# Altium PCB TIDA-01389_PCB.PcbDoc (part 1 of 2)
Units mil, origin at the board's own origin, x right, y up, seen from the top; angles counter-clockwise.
Board outline 3030.03 x 3369.98 mil, 2 copper layers (Top Layer, Bottom Layer), stack 62 mil thick; 50 components, 45 nets, 172 pads, 343 vias.
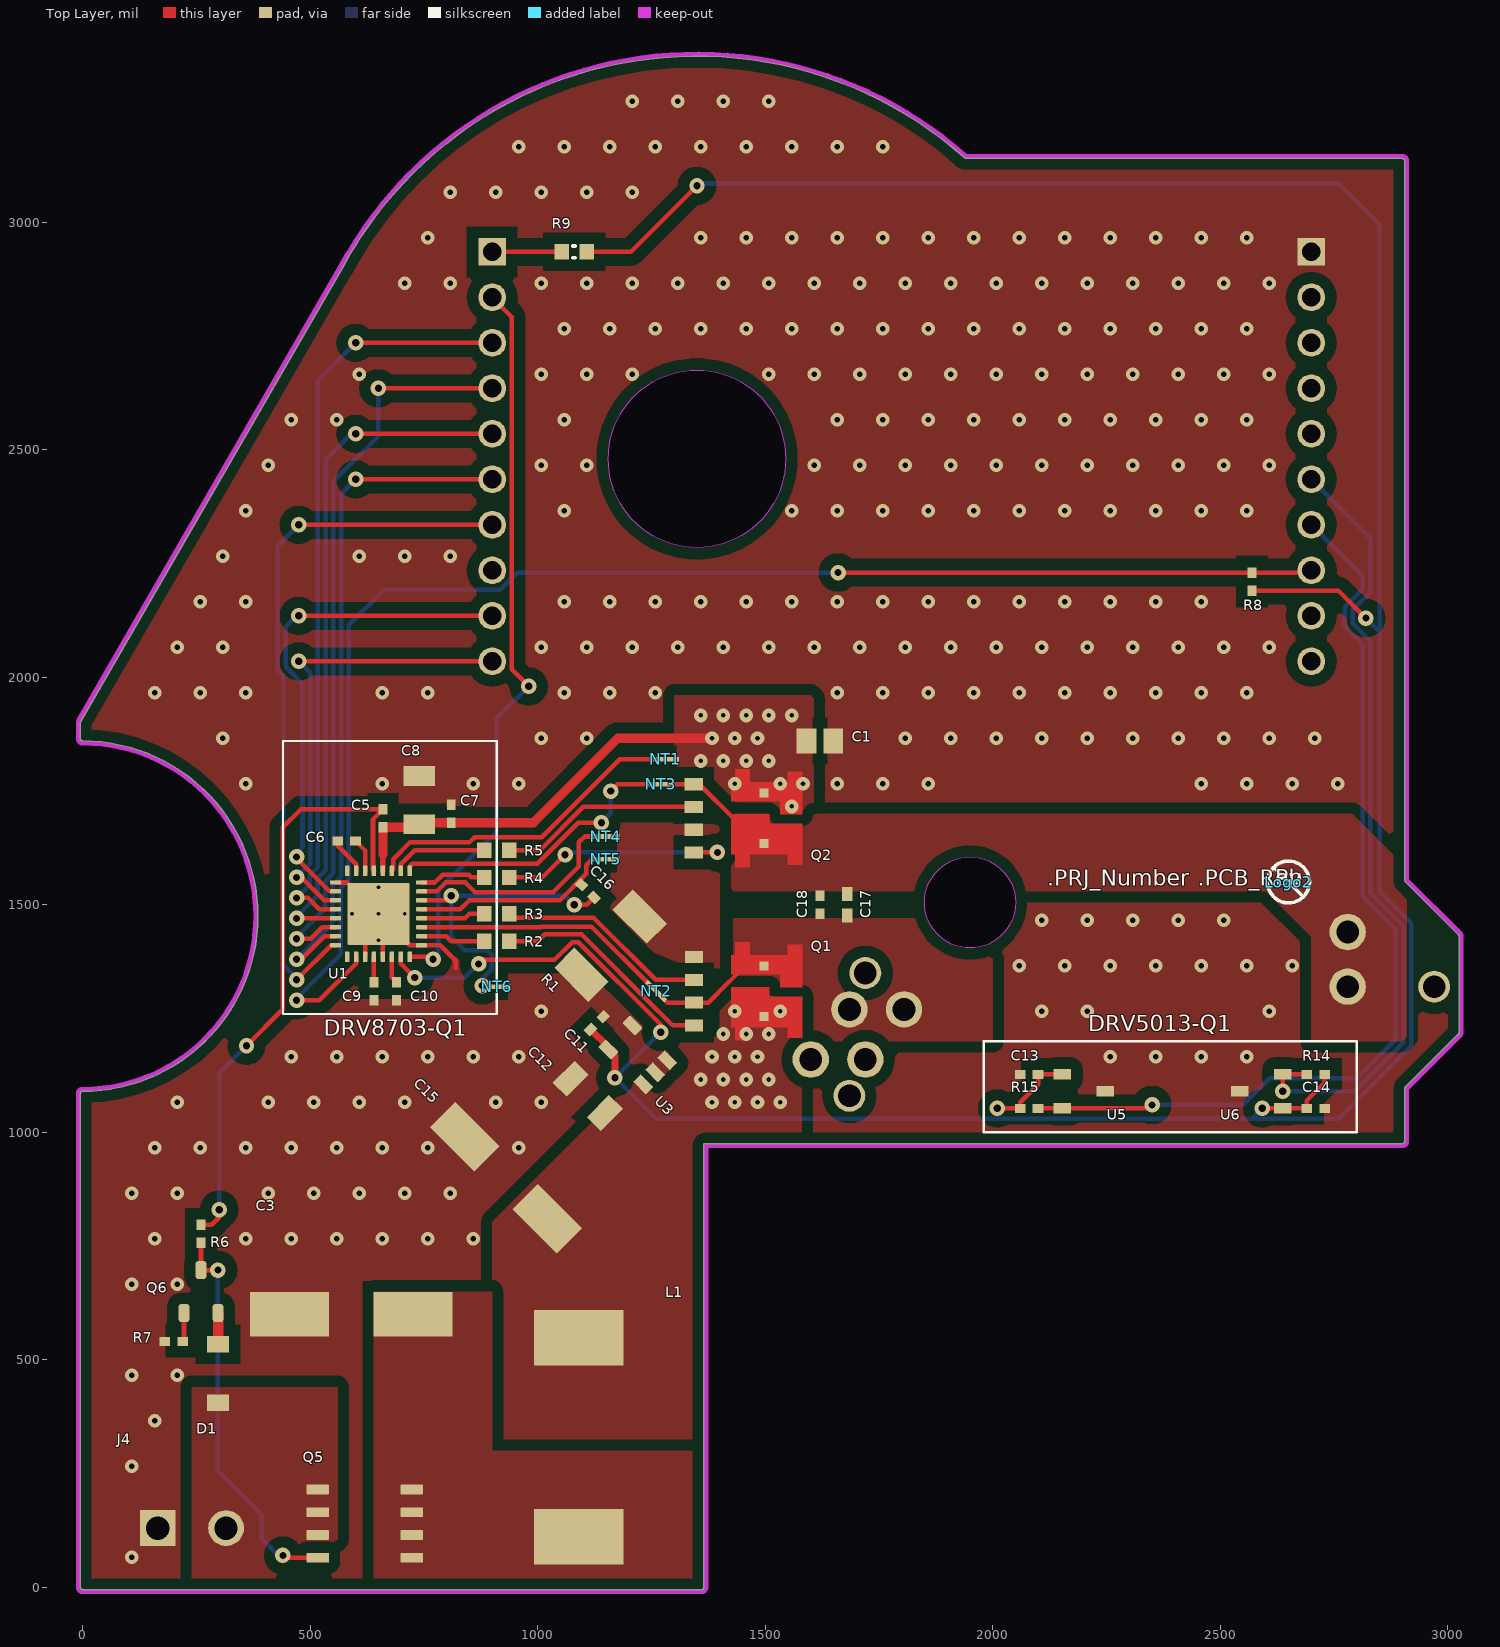
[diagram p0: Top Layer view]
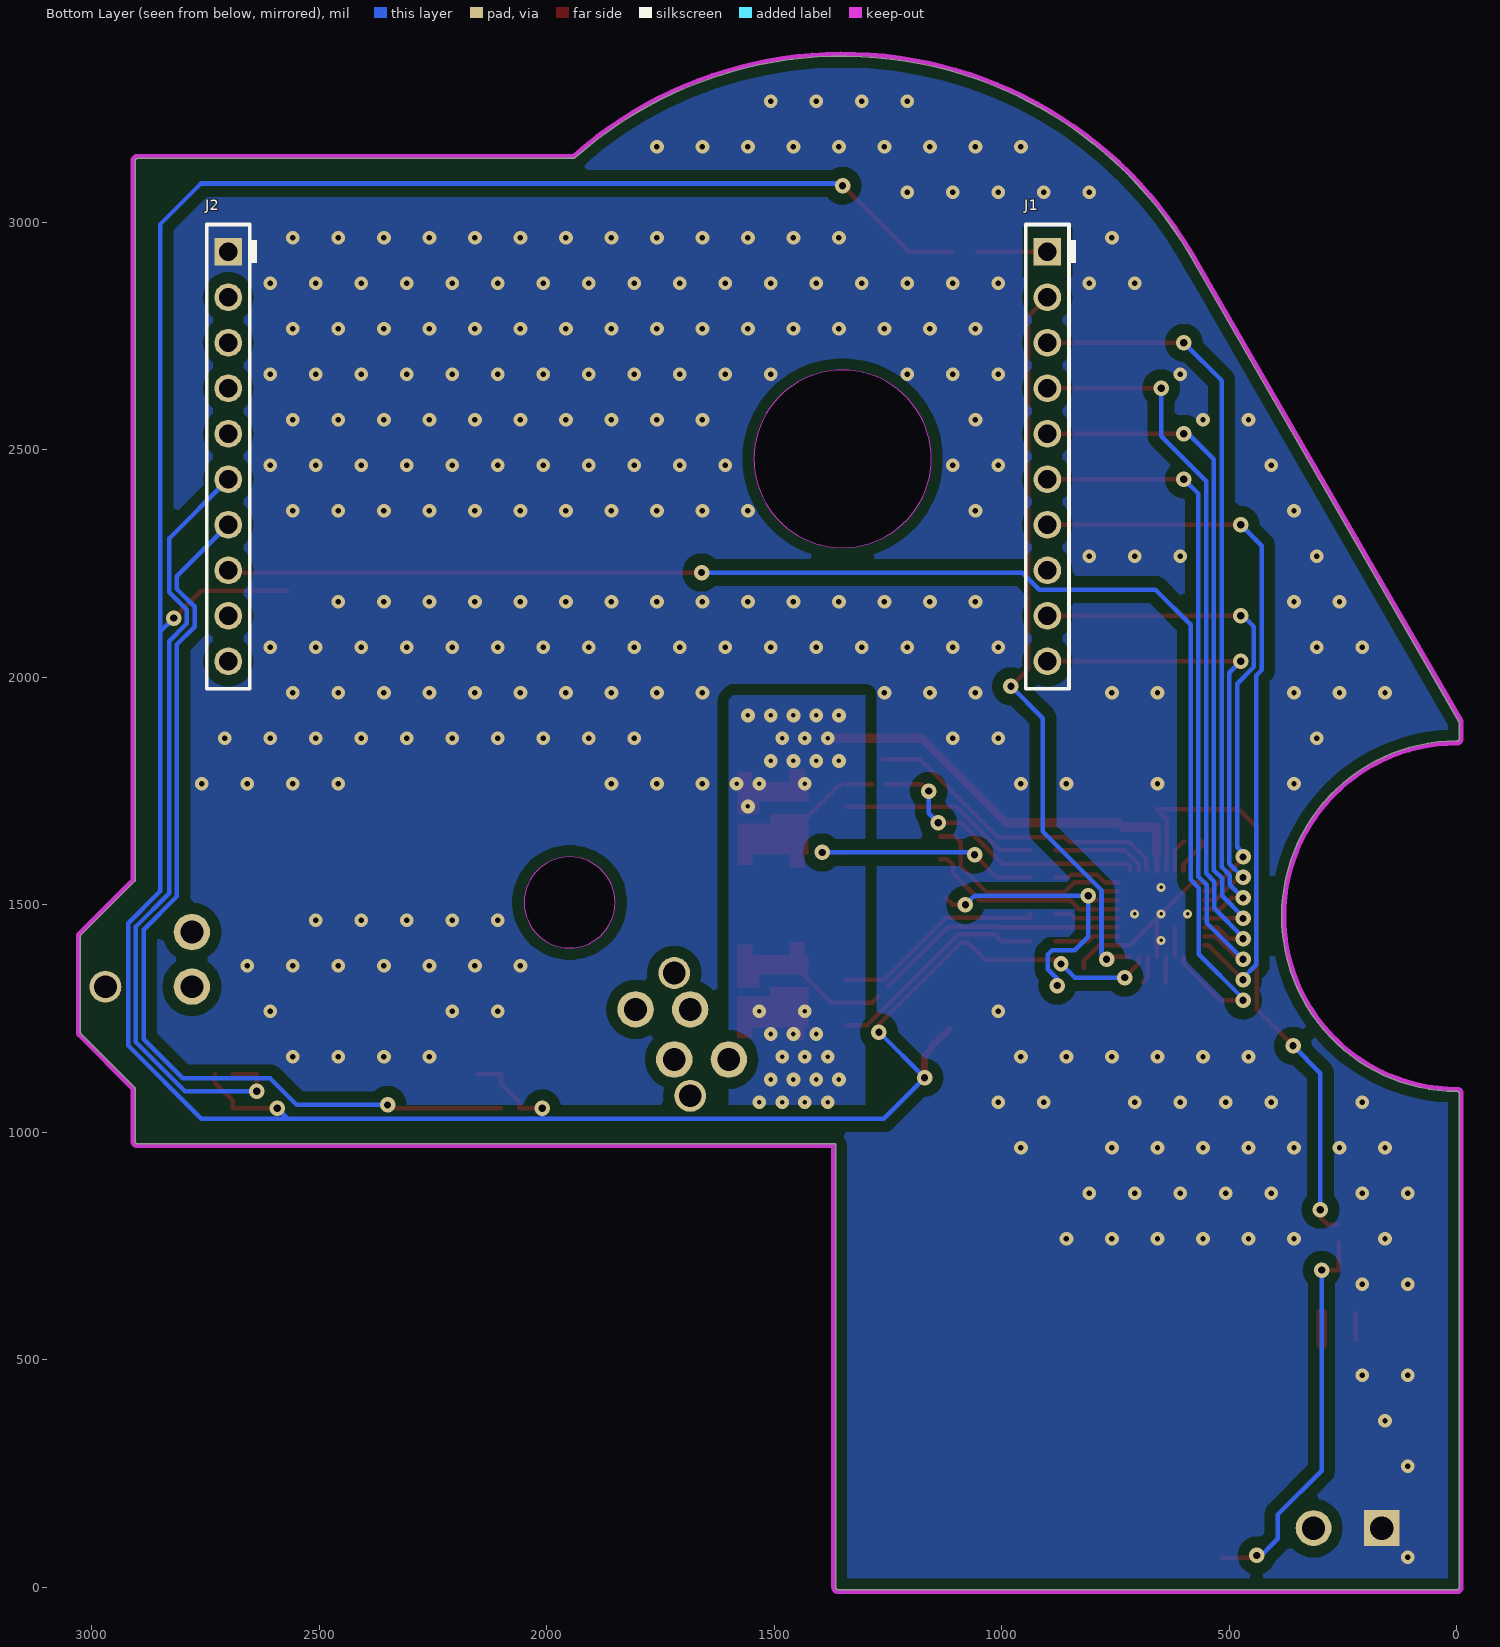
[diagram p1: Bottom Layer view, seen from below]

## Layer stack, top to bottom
Top Solder: solder mask 0.4, Solder Resist, Dk 3.5
Top Layer: signal copper 1.4
Dielectric1: core 59.2, FR-4, Dk 4.8
Bottom Layer: signal copper 1.4
Bottom Solder: solder mask 0.4, Solder Resist, Dk 3.5

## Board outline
0,-5.02 cw(c0,0) -5.02,0.13 -5.02,1085 cw(c0,1085) 0,1090.01 ccw(c0,1475) 384.98,1475 ccw(c0,1475) 0,1859.98 cw(c0,1865) -5.02,1865 -5.02,1900 cw(c0,1900) -4.34,1902.51 571.13,2900.26 cw(c1350,2480) 1936.71,3142.58 cw(c1933.39,3138.83) 1936.95,3142.36 1936.94,3142.37 1939.3,3140.01 2900,3140.01 cw(c2900,3135) 2905.01,3135 2905.01,1552.08 3023.55,1433.55 3023.53,1433.56 cw(c3020,1430) 3025.01,1430 3025.01,1220 cw(c3020,1220) 3023.53,1216.44 3023.55,1216.45 2905.01,1097.92 2905.01,980 cw(c2900,980) 2900,974.98 1365.01,974.98 1365.01,0 cw(c1360,0) 1360,-5.02
cut-out: 1350,2285 cw(c1350,2480) 1155,2480 cw(c1350,2480) 1350,2675 cw(c1350,2480) 1545,2480 cw(c1350,2480)
cut-out: 1950,1405 cw(c1950,1505) 1850,1505 cw(c1950,1505) 1950,1605 cw(c1950,1505) 2050,1505 cw(c1950,1505)

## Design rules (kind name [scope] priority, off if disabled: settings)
AcuteAngle [All] p1: minimum=4.50000000000000E+0001 checktracksonly=FALSE
AssemblyTestPointUsage [All] p1: valid=2
Clearance Clearance_Keepouts [((IsTrack Or IsArc) And Not InPoly) And IsFree and IsKeepOut vs ((IsTrack Or IsArc) And Not InPoly) And IsFree and IsKeepOut] p1: gap=0
Clearance Clearance_BoardEdge_MountingHoles [OnCopper and InComponentClass('Mounting Holes') vs IsKeepOut] p2: gap=40
Clearance Clearance_BoardEdge_Poly [OnCopper and InPoly vs IsKeepOut] p3: gap=25
Clearance Clearance_BoardEdge [OnCopper and Not InComponentClass('Logo') and not InComponentClass('FiducialMark') and not InRegion(1000,500,4000,800) and Not IsKeepout vs IsKeepOut] p4: gap=50
Clearance Clearance_Poly [InPolygon] p5: gap=25
Clearance [All] p6: gap=7
ComponentClearance ComponentClearance_MountingHoles_FiducialMarks [InComponentClass('Mounting Holes') vs InComponentClass('FiducialMark')] p1: gap=50 collisioncheckmode=3 verticalgap=10 showdistances=FALSE
ComponentClearance ComponentClearance_Shunt [InComponentClass('Header') vs InComponentClass('Shunt')] p2: gap=0 collisioncheckmode=3 verticalgap=0 showdistances=FALSE
ComponentClearance ComponentClearance_Logo [InComponentClass('Logo')] p3: gap=50 collisioncheckmode=3 verticalgap=10 showdistances=FALSE
ComponentClearance ComponentClearance_ScrewToNut [(HasFootprint('NY PMS 440 0025 PH')) vs (HasFootprint('Keystone_1902C'))] p4: gap=5 collisioncheckmode=3 verticalgap=10 showdistances=FALSE
ComponentClearance ComponentClearance_MountingHoles [InComponentClass('Mounting Holes')] p5: gap=250 collisioncheckmode=3 verticalgap=100000 showdistances=FALSE
ComponentClearance ComponentClearance_SmallPassives [HasFootprint('0201*') or HasFootprint('0402*') or HasFootprint('0508') or HasFootprint('0603*') or HasFootprint('0612') or HasFootprint('0805*') or HasFootprint('0815*') or HasFootprint('0830*') or HasFootprint('1206*') or HasFootprint('1210*') or HasFootprint('1808*') or HasFootprint('1812*') or HasFootprint('1825*') or HasFootprint('2010*') or HasFootprint('2220*') or HasFootprint('2225*') or HasFootprint('2512*') or HasFootprint('2728*') or HasFootprint('3518*') vs HasFootprint('0201*') or HasFootprint('0402*') or HasFootprint('0508') or HasFootprint('0603*') or HasFootprint('0612') or HasFootprint('0805*') or HasFootprint('0815*') or HasFootprint('0830*') or HasFootprint('1206*') or HasFootprint('1210*') or HasFootprint('1808*') or HasFootprint('1812*') or HasFootprint('1825*') or HasFootprint('2010*') or HasFootprint('2220*') or HasFootprint('2225*') or HasFootprint('2512*') or HasFootprint('2728*') or HasFootprint('3518*')] p6: gap=20 collisioncheckmode=3 verticalgap=10 showdistances=FALSE
ComponentClearance ComponentClearance_THtoSMT [IsThruComponent vs IsSMTComponent] p7: gap=100 collisioncheckmode=3 verticalgap=30 showdistances=FALSE
ComponentClearance ComponentClearance_THtoTH [IsThruComponent vs IsThruComponent] p8: gap=118.11 collisioncheckmode=3 verticalgap=30 showdistances=FALSE
ComponentClearance [All] p9: gap=40 collisioncheckmode=3 verticalgap=10 showdistances=FALSE
DiffPairsRouting [All] p1: maxlimit=100 minlimit=10 mostfreqgap=10 toplayer_minwidth=15 toplayer_maxwidth=15 toplayer_prefwidth=15 bottomlayer_minwidth=15 bottomlayer_maxwidth=15 bottomlayer_prefwidth=15 maxuncoupledlength=1000
FabricationTestPointUsage TestPointUsage [All] p1: valid=2 allowmultiple=FALSE
FabricationTestpoint Testpoint [All] p1: side=3 testpointundercomponent=TRUE minsize=40 maxsize=100 preferedsize=60 minholesize=0 maxholesize=40 preferedholesize=32 testpointgrid=1 allowsidetop=TRUE allowsidebottom=TRUE usegrid=TRUE gridtolerance=0.01
FanoutControl Fanout_LCC [IsLCC] p1: bgadir=Out bgaviamode=Centered fanoutstyle=Auto fanoutdirection=Alternating viagrid=1 // Fanout_LCC (Default Rule)
FanoutControl Fanout_BGA [IsBGA] p2: bgadir=Out bgaviamode=Centered fanoutstyle=Auto fanoutdirection=Alternating viagrid=1 // Fanout_BGA (Default Rule)
FanoutControl Fanout_Default [All] p4: bgadir=Out bgaviamode=Centered fanoutstyle=Auto fanoutdirection=Alternating viagrid=1 // Fanout_Default (Default Rule)
FanoutControl Fanout_Small [(CompPinCount < 5)] p5: bgadir=Out bgaviamode=Centered fanoutstyle=Auto fanoutdirection=OutThenIn viagrid=1 // Fanout_Small (Default Rule)
HoleSize [All] p1: absolutevalues=TRUE maxlimit=251 minlimit=7.5 maxpercent=80.000 minpercent=20.000
MinimumAnnularRing MinimumAnnularRing_ThermalPadVias [IsVia and InAnyComponent] p1: minimumring=5.91
MinimumAnnularRing [All] p2: minimumring=9
MinimumSolderMaskSliver MinimumSolderMaskSliver_Logo [InComponentClass('Logo') vs InComponentClass('Logo')] p1: minsoldermaskwidth=0.7
MinimumSolderMaskSliver [All] p2: minsoldermaskwidth=3.94
PlaneConnect [All] p1: planeconnectstyle=Direct reliefexpansion=10 reliefentries=4 reliefconductorwidth=10 reliefairgap=10
PolygonConnect [All] p1: connectstyle=Direct reliefconductorwidth=10 reliefentries=4 polygonreliefangle="90 Angle" airgapwidth=10
RoutingVias ThermalPadVias [IsVia and InAnyComponent] p1: holewidth=7.87 width=19.68 viastyle="Through Hole" minholewidth=7.87 minwidth=19.68 maxholewidth=12.99 maxwidth=23.62
RoutingVias [All] p2: holewidth=16 width=34 viastyle="Through Hole" minholewidth=7.87 minwidth=26 maxholewidth=40 maxwidth=65
SilkToBoardRegionClearance [Not ((IsComment or IsDesignator) And (Hide <> 'False')) and not InRegion(1000,500,4000,800)] p1:
SilkToSilkClearance SilkToSilkClearance_Pb-FreeLogo [(HasFootprint('Pb-Free_Overlay_Medium') OR HasFootprint('Pb-Free_Overlay_Small')) vs (HasFootprint('Pb-Free_Overlay_Medium') OR HasFootprint('Pb-Free_Overlay_Small'))] p1: silktosilkclearance=0
SilkToSilkClearance [All] p2: silktosilkclearance=4
SilkToSolderMaskClearance SilkToComonentPadClearance [IsPad and InAnycomponent] p1: minsilkscreentomaskgap=5 clearancetoexposedcopper=TRUE
SilkToSolderMaskClearance "Silk to Solder Mask Opening" [All] p2: minsilkscreentomaskgap=4 clearancetoexposedcopper=FALSE
SolderMaskExpansion [All] p1: expansion=1.97
Width [All] p1: maxlimit=100 minlimit=6 preferedwidth=10 checkconnectedcopper=TRUE
15 further rules are at their usual default settings.

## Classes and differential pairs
component class AssemblyNote: ZZ1 ZZ2 ZZ3
component class TIDA-01389_Hardware: Logo2 ZZ1 ZZ2 ZZ3
component class TIDA-01389_Sch: C1 C3 C5 C6 C7 C8 C9 C10 C11 C12 C13 C14 C15 C16 C17 C18 D1 J1 J2 J4 L1 NT1 NT2 NT3 NT4 NT5 NT6 Q1 Q2 Q5 Q6 R1 R2 R3 R4 R5 R6 R7 R8 R9 R14 R15 U1 U3 U5 U6

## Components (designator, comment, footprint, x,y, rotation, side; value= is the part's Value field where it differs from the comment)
C1 "GRM21BR71H105KA12L" 0805L 1620,1860 r0 top
C3 "EEE-FPV391UAP" CAPAE1030X1080 590,600 r180 top
C5 "C1005X5R1C105K050BC" 0402L#1 660,1690 r90 top
C6 "GCM155R71H104KE02D" 0402L#1 580,1640 r0 top
C7 "GRM155R61H104ME14D" 0402L#1 810,1700 r90 top
C8 "C3216X5R1H106K160AB" 1206_180L 740,1730 r90 top
C9 "GRM155R70J105MA12D" 0402L#1 640,1310 r270 top
C10 "GRM155R70J105MA12D" 0402L#1 690,1310 r270 top
C11 "GRM155R60J475ME47D" 0402L#1 1130,1240 r45 top
C12 "C3216X5R1H106K160AB" 1206_180L 1110,1080 r135 top
C13 "GRM155R61H104ME14D" 0402L#1 2080,1127.4 r180 top
C14 "GRM155R61H104ME14D" 0402L#1 2710,1052.6 r0 top
C15 "PCV1J390MCL2GS" PCV_800x1200 930,900 r135 top
C16 "GRM155R71C102KA01D" 0402L#1 1109.95,1529.95 r315 top
C17 "GCM155R71C104KA55D" 0402 1680,1500 r90 top
C18 "GRM155R71C102KA01D" 0402L#1 1620,1500 r90 top
D1 "1N4148W-TP" SOD-123 297.4,470 r90 top
J1 "SSQ-110-01-T-S" Samtec_SSQ-110-01-x-S 900,2485 r270 bottom
J2 "SSQ-110-01-T-S" Samtec_SSQ-110-01-x-S 2700,2485 r270 bottom
J4 "691214310002" Wurth_691214310002 240,130 r0 top
L1 "SRP1265A-100M" SRP1265A 1090,330 r90 top
Logo2 "Pb-Free Symbol" Pb-Free_Overlay_Small 2650,1550 r0 top
NT1 "Net-Tie" Net-Tie_10milWide_30milLong 1280,1820 r180 top net-tie
NT2 "Net-Tie" Net-Tie_10milWide_30milLong 1260,1310 r315 top net-tie
NT3 "Net-Tie" Net-Tie_10milWide_30milLong 1270,1765 r180 top net-tie
NT4 "Net-Tie" Net-Tie_10milWide_30milLong 1150,1650 r180 top net-tie
NT5 "Net-Tie" Net-Tie_10milWide_30milLong 1150,1600 r180 top net-tie
NT6 "Net-Tie" Net-Tie_10milWide_30milLong 910,1320 r180 top net-tie
Q1 "SQJ940EP-T1-GE3" PowerPAK_SO-8L_Dual 1450.08,1309.92 r0 top
Q2 "SQJ940EP-T1-GE3" PowerPAK_SO-8L_Dual 1450,1690 r0 top
Q5 "SQ4470EY-T1-GE3" SOIC-8L 620,140 r0 top
Q6 "MMBTA06-7-F" SOT-23 260,650 r90 top
R1 "CSRN2010FK40L0" 2010 1160,1410 r45 top
R2 "CRCW06030000Z0EA" 0603L 910,1420 r180 top
R3 "CRCW06030000Z0EA" 0603L 910,1480 r180 top
R4 "CRCW06030000Z0EA" 0603L 910,1560 r0 top
R5 "CRCW06030000Z0EA" 0603L 910,1620 r0 top
R6 "CRCW040210K0JNED" 0402L#2 260,760 r90 top
R7 "CRCW040243K0JNED" 0402L#1 200,540 r0 top
R8 "CRCW040210K0JNED" 0402L#1 2570,2210 r270 top
R9 "CRCW06030000Z0EA" 0603L 1080,2935 r0 top
R14 "CRCW040210K0JNED" 0402L#1 2710,1127.4 r0 top
R15 "CRCW040210K0JNED" 0402L#1 2080,1052.6 r180 top
U1 "DRV8703QRHBRQ1" RHB0032E 650,1480 r0 top
U3 "TPS7B6933QDBVRQ1" DBV0005A_N 1220,1170 r135 top
U5 "DRV5013ADQDBZRQ1" DBZ0003A_N 2200,1090 r0 top
U6 "DRV5013ADQDBZRQ1" DBZ0003A_N 2590,1090 r180 top
ZZ1 "These assemblies are ESD sensitive, ESD precautions shall be observed." AssemblyNote 55,3699.11 r0 top
ZZ2 "These assemblies must be clean and free from flux and all contaminants. Use of no clean flux is not acceptable." AssemblyNote 55,3610.56 r0 top
ZZ3 "These assemblies must comply with workmanship standards IPC-A-610 Class 2, unless otherwise specified." AssemblyNote 55,3522 r0 top

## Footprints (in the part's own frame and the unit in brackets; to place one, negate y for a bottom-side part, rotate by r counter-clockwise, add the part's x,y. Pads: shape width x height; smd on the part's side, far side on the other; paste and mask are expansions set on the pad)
0402 [mm] "0402 from SM-752 data"
  rect 0.8x0.6 smd: 1(-0.6,0) 2(0.6,0)
  body extent -0.55,-0.3 0.55,0.3, height 0.6
0402L#1 [mm] "0402 from SM-752 data"
  rect 0.6x0.5 smd: 1(-0.5,0) 2(0.5,0)
  body extent -0.55,-0.3 0.55,0.3, height 0.6
0402L#2 [mm] "0402 from SM-752 data"
  rect 0.6x0.5 smd: 1(-0.068,0) 2(0.932,0)
  body extent -0.12,-0.3 0.98,0.3, height 0.6
0603L [mm] "0603 from SM-752 data"
  rect 0.8x0.85 smd: 1(-0.7,0) 2(0.7,0)
  body extent -0.87,-0.47 0.87,0.47, height 1
0805L [mm] "0805 from SM-752 data"
  rect 1.1x1.4 smd: 1(-0.75,0) 2(0.75,0)
  body extent -1.1,-0.72 1.1,0.72, height 1.45
1206_180L [mm] "1206_180"
  rect 1.1x1.75 smd: 1(-1.35,0) 2(1.35,0)
  body extent -1.75,-0.95 1.75,0.95, height 1.8
2010 [mm] "Chip Capacitor, Body 5.08x2.54mm, IPC Medium Density"
  rect 1.6x2.7 smd: 1(-2.3,0) 2(2.3,0)
  body extent -2.73,-1.45 2.73,1.45, height 1.66
AssemblyNote [mil] "Assembly Note"
CAPAE1030X1080 [mm] "10.3 x 10.3 mm base"
  rect 4.4x2.5 smd: 1(-3.45,0) 2(3.45,0)
  body extent -5.25,-5.25 5.25,5.25, height 10.5
DBV0005A_N [mm] "SOT23, 5-Leads, Body 2.9x1.6mm, Pitch 0.95mm, Lead Span 2.8mm, IPC Medium Density"
  rrect17% 1x0.6 smd: 1(-1.375,0.95) 2(-1.375,0) 3(-1.375,-0.95) 4(1.375,-0.95) 5(1.375,0.95)
  body extent -1.42,-1.46 1.42,1.46, height 1.09
DBZ0003A_N [mm] "SOT23, 3-Leads, Body 2.9x1.3mm, Pitch 0.95mm, Lead Span 2.4mm, IPC Medium Density"
  rrect17% 1x0.6 smd: 1(-1.2,0.95) 2(-1.2,-0.95) 3(1.2,0)
  body extent -1.26,-1.46 1.26,1.46, height 0.98
Net-Tie_10milWide_30milLong [mil] "10mil net tie, no solder mask opening, no solder paste"
  rect 30x10 smd paste-5 mask-5: 1(-15,0) 2(15,0)
Pb-Free_Overlay_Small [mil]
  silkscreen extent -46,-46 46,46
PCV_800x1200 [mm] "SMD, 2-Leads, Dia 8mm"
  rect 3.5x2 smd: 1(-3.25,0) 2(3.25,0)
  body extent -4.25,-4.25 4.25,4.25, height 12.01
PowerPAK_SO-8L_Dual [mm] "SMD, 6-Leads, Body 4.9x4.37mm"
  rect 1.02x0.68 smd: 1(-2.715,1.905) 2(-2.715,0.635) 3(-2.715,-0.635) 4(-2.715,-1.905)
  rect 0.5x0.5 smd paste+0 mask+0.102: 5(1.2,-1.4) 6(1.2,1.4)
  Top Layer region: -0.635,0.215 1.505,0.215 1.505,-0.295 3.325,-0.295 3.325,-2.6 2.515,-2.6 2.515,-2.015 0.405,-2.015 0.405,-2.725 -0.405,-2.725 -0.405,-2.015 -0.635,-2.015
  Top Layer region: -0.405,2.725 -0.405,2.015 -0.635,2.015 -0.635,0.955 2.115,0.955 2.115,0.215 3.325,0.215 3.325,2.6 2.515,2.6 2.515,2.015 0.405,2.015 0.405,2.725
  body extent -2.29,-2.55 2.29,2.55, height 1.27
RHB0032E [mm] "QFN, 32-Leads, Body 5x5mm, Pitch 0.5mm, Thermal Pad 3.45x3.45mm, TI Recommended"
  rrect40% 0.6x0.25 smd: 1(-2.4,1.75) 2(-2.4,1.25) 3(-2.4,0.75) 4(-2.4,0.25) 5(-2.4,-0.25) 6(-2.4,-0.75) 7(-2.4,-1.25) 8(-2.4,-1.75) 17(2.4,-1.75) 18(2.4,-1.25) 19(2.4,-0.75) 20(2.4,-0.25) 21(2.4,0.25) 22(2.4,0.75) 23(2.4,1.25) 24(2.4,1.75)
  rrect40% 0.25x0.6 smd: 9(-1.75,-2.4) 10(-1.25,-2.4) 11(-0.75,-2.4) 12(-0.25,-2.4) 13(0.25,-2.4) 14(0.75,-2.4) 15(1.25,-2.4) 16(1.75,-2.4) 25(1.75,2.4) 26(1.25,2.4) 27(0.75,2.4) 28(0.25,2.4) 29(-0.25,2.4) 30(-0.75,2.4) 31(-1.25,2.4) 32(-1.75,2.4)
  rrect3% 3.45x3.45 smd paste-1.725: 33(0,0)
  rrect7% 1.49x1.49 on Top Paste: ""(-0.845,-0.845) ""(-0.845,0.845) ""(0.845,-0.845) ""(0.845,0.845)
  body extent -2.57,-2.58 2.58,2.58, height 1.01
Samtec_SSQ-110-01-x-S [mm] "Receptacle, 2.54mm, 10x1, TH"
  rect 1.55x1.55 hole 1.02: 1(-11.43,0)
  round 1.55 hole 1.02: 2(-8.89,0) 3(-6.35,0) 4(-3.81,0) 5(-1.27,0) 6(1.27,0) 7(3.81,0) 8(6.35,0) 9(8.89,0) 10(11.43,0)
  silkscreen extent -12.95,-1.21 12.95,1.6, body extent -12.95,-1.21 12.95,1.21, height 8.51
SOD-123 [mm] "On Semi recommended land pattern"
  rect 0.915x1.22 smd: 1(-1.638,0) 2(1.637,0)
  body extent -1.93,-0.9 1.93,0.9, height 1.35
SOIC-8L [mm] "Duplicate of SO-8.  SOIC, 8-Leads, Body 5.0x4.0mm (max), Pitch 1.27mm, IPC Most Density"
  rrect18% 1.25x0.55 smd: 1(-2.625,1.905) 2(-2.625,0.635) 3(-2.625,-0.635) 4(-2.625,-1.905) 5(2.625,-1.905) 6(2.625,-0.635) 7(2.625,0.635) 8(2.625,1.905)
  body extent -3,-2.45 3,2.45, height 1.63
SOT-23 [mm] "SOT23, 3-Leads, Body 2.9x1.3mm, Pitch 0.95mm, Lead Span 2.5mm, IPC Medium Density"
  rrect50% 1x0.6 smd: 1(-1.2,0.95) 2(-1.2,-0.95) 3(1.2,0)
  body extent -1.16,-1.45 1.21,1.45, height 1
SRP1265A [mm] "BOURNS"
  rect 3.1x5 smd: 1(-5.55,0) 2(5.55,0)
  body extent -6.95,-6.4 6.95,6.4, height 6.4
Wurth_691214310002 [mm] "WE"
  rect 2x2 hole 1.3: 1(-1.905,0)
  round 2 hole 1.3: 2(1.905,0)
  body extent -4.12,-3.5 3.9,3.9, height 8.52

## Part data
C1: "CAP, CERM, 1 µF, 50 V, +/- 10%, X7R, 0805"
C3: "CAP, AL, 390 µF, 35 V, +/- 20%, 0.08 ohm, AEC-Q200 Grade 2, SMD"
C5: "CAP, CERM, 1 µF, 16 V, +/- 10%, X5R, 0402"
C6: "CAP, CERM, 0.1 µF, 50 V, +/- 10%, X7R, AEC-Q200 Grade 1, 0402"
C7 C13 C14: "CAP, CERM, 0.1 µF, 50 V, +/- 20%, X5R, 0402"
C8 C12: "CAP, CERM, 10 µF, 50 V, +/- 10%, X5R, 1206"
C9 C10: "CAP, CERM, 1 µF, 6.3 V, +/- 20%, X7R, 0402"
C11: "CAP, CERM, 4.7 µF, 6.3 V, +/- 20%, X5R, 0402"
C15: "CAP, Aluminum Polymer, 39 µF, 63 V, +/- 20%, 0.029 ohm, AEC-Q200 Grade 2, D8xL12mm SMD"
C16 C18: "CAP, CERM, 1000 pF, 16 V, +/- 10%, X7R, 0402"
C17: "CAP, CERM, 0.1 µF, 16 V, +/- 10%, X7R, 0402"
D1: "Diode, Switching, 100 V, 0.15 A, SOD-123"
J1 J2: "Receptacle, 2.54mm, 10x1, Tin, TH"
J4: "Terminal Block, 2x1, 3.81mm, 24-16 AWG, 10A, 300VAC, TH"
L1: "Inductor, Shielded, 10 µH, 10 A, 0.0132 ohm, AEC-Q200 Grade 0, SMD"
Logo2: library part Pb-Free
NT1 NT2 NT3 NT4 NT5 NT6: "Single point connection between nets."
Q1 Q2: "MOSFET, N-CH, 40 V, 15 A, AEC-Q101, PowerPAK SO-8 Dual Asymmetric"
Q5: "MOSFET, N-CH, 60 V, 16 A, SOIC-8"
Q6: library part "MMBTA06-7-F, Diodes Inc.", "Transistor, NPN, 80 V, 0.5 A, SOT-23"
R1: "RES, 0.04, 1%, 1 W, 2010"
R2 R3 R4 R5 R9: "RES, 0, 5%, 0.1 W, 0603"
R6 R8 R14 R15: "RES, 10 k, 5%, 0.063 W, 0402"
R7: "RES, 43 k, 5%, 0.063 W, 0402"
U1: "Full-Bridge Automotive Gate Driver, RHB0032E"
U3: "High Voltage Ultra Low Iq - Low Drop Out Regulator, DBV0005A"
U5 U6: "Automotive Digital-Latch Hall Effect Sensor, DBZ0003A"
ZZ1 ZZ2 ZZ3: library part AssemblyNote

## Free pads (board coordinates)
  round 70 hole 50: 0(1685,1080) 0(1720,1350) 0(2970,1320)
  round 80 hole 50: 1(1720,1160) 1(1805,1270) 1(2780,1440) 2(1600,1160) 2(1685,1270) 2(2780,1320)

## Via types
v1: diameter 30, hole 12, Top Layer to Bottom Layer, tented both sides, 267 vias
v2: diameter 34, hole 16, Top Layer to Bottom Layer, 39 vias
v3: diameter 30, hole 10, Top Layer to Bottom Layer, tented both sides, 32 vias
v4: diameter 19.68, hole 7.87, Top Layer to Bottom Layer, 5 vias

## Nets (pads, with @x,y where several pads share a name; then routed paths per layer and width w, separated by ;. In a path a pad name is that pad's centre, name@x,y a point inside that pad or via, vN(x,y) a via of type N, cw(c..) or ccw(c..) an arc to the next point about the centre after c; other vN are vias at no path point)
+V_BAT: D1.1 J4.2 Q5.1 Q5.2 Q5.3
+V_SWITCH: C3.1 L1.1 Q5.5 Q5.6 Q5.7 Q5.8
DOWN: J2.10 | length 7.5
  Top Layer w10: J2.10@2694.68,2040.32 J2.10@2700,2035
GH1: R2.2 U1.18 | length 142.4
  Top Layer w10: U1.18@744.49,1430.79 799.21,1430.79 810,1420 R2.2@882.44,1420
GH2: R5.1 U1.26 | length 210.7
  Top Layer w10: U1.26@699.21,1574.49 699.21,1589.21 730,1620 R5.1@882.44,1620
GL1: R3.2 U1.20 | length 142
  Top Layer w10: U1.20@744.49,1470.16 840.16,1470.16 850,1480 R3.2@882.44,1480
GL2: R4.1 U1.24 | length 147.5
  Top Layer w10: U1.24@744.49,1548.9 773.84,1548.9 790.95,1566 848.04,1566 854.04,1560 R4.1@882.44,1560
GND: C1.2 C3.2 C7.2 C8.2 C9.2 C10.2 C11.2 C12.2 C13.2 C14.2 C15.2 J2.1 J4.1 NT6.1 R1.1 R7.1 U1.1 U1.11 U1.13 U1.17 U1.33 U3.2 U3.3 U3.4 U5.3 U6.3 | length 502.4
  Top Layer w10: U1.1@555.51,1548.9 581.1,1548.9 v4(650,1480) U1.33@659.84,1470.16 ; U1.11@620.47,1385.51 U1.33@620.47,1450.47 ; U1.13@659.84,1385.51 U1.33@659.84,1470.16 ; 820,1360 820,1377.21 786.1,1411.1 U1.17@744.49,1411.1 718.9,1411.1 U1.33@659.84,1470.16
  other v1: 108,66 108,266 158,366 108,466 208,466 108,666 208,666 158,766 358,766 458,766 558,766 658,766 758,766 858,766 108,866 208,866 408,866 508,866 608,866 708,866 808,866 158,966 258,966 358,966 458,966 558,966 658,966 758,966 958,966 208,1066 408,1066 508,1066 608,1066 708,1066 908,1066 1008,1066 458,1166 558,1166 658,1166 758,1166 858,1166 958,1166 2258,1166 2358,1166 2458,1166 2558,1166 1008,1266 2108,1266 2208,1266 2608,1266 2058,1366 2158,1366 2258,1366 2358,1366 2458,1366 2558,1366 2658,1366 2108,1466 2208,1466 2308,1466 2408,1466 2508,1466 358,1766 658,1766 858,1766 958,1766 1658,1766 1758,1766 1858,1766 2458,1766 2558,1766 2658,1766 2758,1766 308,1866 1008,1866 1108,1866 1808,1866 1908,1866 2008,1866 2108,1866 2208,1866 2308,1866 2408,1866 2508,1866 2608,1866 2708,1866 158,1966 258,1966 358,1966 658,1966 758,1966 1058,1966 1158,1966 1258,1966 1658,1966 1758,1966 1858,1966 1958,1966 2058,1966 2158,1966 2258,1966 2358,1966 2458,1966 2558,1966 208,2066 308,2066 1008,2066 1108,2066 1208,2066 1308,2066 1408,2066 1508,2066 1608,2066 1708,2066 1808,2066 1908,2066 2008,2066 2108,2066 2208,2066 2308,2066 2408,2066 2508,2066 2608,2066 258,2166 358,2166 1058,2166 1158,2166 1258,2166 1358,2166 1458,2166 1558,2166 1658,2166 1758,2166 1858,2166 1958,2166 2058,2166 2158,2166 2258,2166 2358,2166 2458,2166 308,2266 608,2266 708,2266 808,2266 358,2366 1058,2366 1558,2366 1658,2366 1758,2366 1858,2366 1958,2366 2058,2366 2158,2366 2258,2366 2358,2366 2458,2366 2558,2366 408,2466 1008,2466 1108,2466 1608,2466 1708,2466 1808,2466 1908,2466 2008,2466 2108,2466 2208,2466 2308,2466 2408,2466 2508,2466 2608,2466 458,2566 558,2566 1058,2566 1658,2566 1758,2566 1858,2566 1958,2566 2058,2566 2158,2566 2258,2566 2358,2566 2458,2566 2558,2566 608,2666 1008,2666 1108,2666 1208,2666 1508,2666 1608,2666 1708,2666 1808,2666 1908,2666 2008,2666 2108,2666 2208,2666 2308,2666 2408,2666 2508,2666 2608,2666 1058,2766 1158,2766 1258,2766 1358,2766 1458,2766 1558,2766 1658,2766 1758,2766 1858,2766 1958,2766 2058,2766 2158,2766 2258,2766 2358,2766 2458,2766 2558,2766 708,2866 808,2866 1008,2866 1108,2866 1208,2866 1308,2866 1408,2866 1508,2866 1608,2866 1708,2866 1808,2866 1908,2866 2008,2866 2108,2866 2208,2866 2308,2866 2408,2866 2508,2866 2608,2866 758,2966 1358,2966 1458,2966 1558,2966 1658,2966 1758,2966 1858,2966 1958,2966 2058,2966 2158,2966 2258,2966 2358,2966 2458,2966 2558,2966 808,3066 908,3066 1008,3066 1108,3066 1208,3066 958,3166 1058,3166 1158,3166 1258,3166 1358,3166 1458,3166 1558,3166 1658,3166 1758,3166 1208,3266 1308,3266 1408,3266 1508,3266
  other v4: 650,1421.93 591.93,1480 708.07,1480 650,1538.07
HALL_1: J2.6 R14.1 U6.2 | length 1754.5
  Top Layer w10: v2(2637.24,1090) U6.2@2637.24,1127.4 R14.1@2690.32,1127.4
  Bottom Layer w10: v2(2637.24,1090) 2795.27,1090 2903,1197.73 2903,1452.27 2830,1525.27 2830,2079 2791.02,2117.99 2791.02,2148 2830,2186.98 2830,2305 J2.6@2700,2435
HALL_2: J2.7 R15.1 U5.2 | length 2088.9
  Top Layer w10: R15.1@2099.68,1052.6 2342.6,1052.6 v2(2350,1060)
  Bottom Layer w10: v2(2350,1060) 2549.24,1060 2608.24,1119 2800.23,1119 2886,1204.77 2886,1445.23 2813,1518.23 2813,2071.96 2774.02,2110.95 2774.02,2155.04 2813,2194.03 2813,2222 J2.7@2700,2335
IN1/PH: J1.9 U1.2 | length 1109.4
  Top Layer w10: v2(470,1605) 470,1601.86 542.65,1529.21 U1.2@555.51,1529.21 ; v2@470,2135 J1.9@900,2135
  Bottom Layer w10: v2(470,1605) 470,1613.22 483,1626.22 483,1985.99 446,2022.99 446,2111 v2@470,2135
  other v2: 475,2135
IN2/EN: J1.10 U1.3 | length 1029.2
  Top Layer w10: v2(470,1560) 480,1560 530.47,1509.53 U1.3@555.51,1509.53 ; v2(475,2035) J1.10@900,2035
  Bottom Layer w10: v2(470,1560) 500,1590 500,2010 v2(475,2035)
NetC6_1: C6.1 U1.31 | length 82.3
  Top Layer w10: C6.1@560.32,1640 560.32,1629.68 600.79,1589.21 U1.31@600.79,1574.49
NetC6_2: C6.2 U1.30 | length 74.1
  Top Layer w10: C6.2@599.69,1640 620.47,1619.21 U1.30@620.47,1574.49
NetC9_1: C9.1 U1.12 | length 55.7
  Top Layer w10: C9.1@640,1329.68 U1.12@640,1385.35
NetC10_1: C10.1 U1.14 | length 60.2
  Top Layer w10: U1.14@679.53,1385.51 679.53,1340.16 C10.1@690,1329.68
NetC17_1: C17.1 C18.1 NT2.2 pad.1@1805,1270 pad.2@1685,1270 Q1.3 Q1.6 | length 244.8
  Top Layer w10: NT2.2@1270.61,1299.39 1285.08,1284.92 Q1.3@1343.19,1284.92 1374.64,1284.92 1420.11,1330.39 1420.39,1330.39 1470,1380
NetC17_2: C17.2 C18.2 NT3.1 pad.1@2780,1440 pad.2@2780,1320 Q2.1 Q2.5 | length 178.3
  Top Layer w10: NT3.1@1285,1765 Q2.1@1343.11,1765 ; Q2.1@1355,1765 1440,1680
NetD1_2: D1.2 Q6.2 | length 68.3
  Top Layer w23: D1.2@297.4,534.47 Q6.2@297.4,602.76
NetJ1_1: J1.1 R9.1 | length 152.4
  Top Layer w10: J1.1@900,2935 R9.1@1052.44,2935
NetNT1_2: NT1.2 U1.27 | length 700.4
  Top Layer w10: U1.27@679.53,1574.49 682.21,1577.17 682.21,1599.82 719.39,1637 849.99,1637 861.72,1648.73 1008.62,1648.73 1179.89,1820 NT1.2@1265,1820
NetNT4_1: NT4.1 NT5.1 Q1.1 Q2.3 R1.2
NetQ1_2: Q1.2 R3.1 | length 471
  Top Layer w10: R3.1@937.56,1480 937.56,1471 1123.04,1471 1259.12,1334.92 Q1.2@1343.19,1334.92
NetQ1_4: Q1.4 R2.1 | length 494.6
  Top Layer w10: R2.1@937.56,1420 1000.31,1420 1015.13,1434.82 1096.15,1434.82 1265.04,1265.93 1265.3,1265.93 1296.31,1234.92 Q1.4@1343.19,1234.92
NetQ2_2: Q2.2 R5.2 | length 444.9
  Top Layer w10: R5.2@937.56,1620 1004.95,1620 1099.95,1715 Q2.2@1343.11,1715
NetQ2_4: Q2.4 R4.2 | length 525
  Top Layer w10: R4.2@937.56,1560 1010,1560 v2(1060,1610) ; Q2.4@1343.11,1615 v2(1395,1615)
  Bottom Layer w10: v2@1065,1615 v2(1395,1615)
NetQ5_4: Q5.4 Q6.3 R6.1 | length 882.4
  Top Layer w10: R6.1@260,757.32 Q6.3@260,697.24 v2(297.24,697.24) ; v2(440,70) 445,65 Q5.4@516.65,65
  Bottom Layer w10: v2(297.24,697.24) 297.24,256.29 393.53,160 393.53,106.47 440,60 v2(440,70)
NetQ6_1: Q6.1 R7.2 | length 59.8
  Top Layer w10: R7.2@222.6,542.91 Q6.1@222.6,602.76
NFAULT: J2.8 R8.1 U1.10 | length 3209.2
  Top Layer w10: v2(470,1290) 520,1290 600.79,1370.79 U1.10@600.79,1385.51 ; v2(1660,2230) J2.8@2695,2230
  Bottom Layer w10: v2(470,1290) 470,1293.99 567,1390.99 567,1536.79 585,1554.79 585,2115 662.49,2192.49 917.61,2192.49 955.12,2230 v2(1660,2230)
PINCH: J2.3
PVDD: C1.1 C5.1 C7.1 C8.1 C12.1 C15.1 L1.2 NT1.1 Q1.5 Q2.6 U1.28 U3.1 | length 915.4
  Top Layer w12: U1.28@659.84,1574.49 659.84,1639.84
  Top Layer w20: 660,1610.16 C5.1@660,1670.32 C8.1@733.46,1670.32 ; C8.1@743.46,1680.32 C7.1@810,1680.32 990.32,1680.32 1176,1866 v3(1383,1866)
  other v3: 1383,1066 1433,1066 1483,1066 1533,1066 1358,1116 1408,1116 1458,1116 1508,1116 1383,1166 1433,1166 1483,1166 1408,1216 1458,1216 1508,1216 1433,1266 1533,1266 1558,1716 1433,1766 1533,1766 1583,1766 1358,1816 1408,1816 1458,1816 1508,1816 1433,1866 1483,1866 1358,1916 1408,1916 1458,1916 1508,1916 1558,1916
SCLK: J1.6 U1.7 | length 1509.4
  Top Layer w10: v2@480,1380 530.79,1430.79 U1.7@555.51,1430.79 ; v2(600,2435) J1.6@900,2435
  Bottom Layer w10: v2@470,1383.99 v2(470,1380) 550,1460 550,1543.83 568,1561.83 568,2403 v2(600,2435)
SCS: J1.5 U1.5 | length 1504.4
  Top Layer w10: v2@470,1460 480.16,1470.16 U1.5@555.51,1470.16 ; v2(600,2535) J1.5@900,2535
  Bottom Layer w10: v2(470,1470) 470,1473.99 516,1519.99 516,1557.92 534,1575.92 534,2479 v2@590,2535
SDI: J1.4 U1.6 | length 1630.6
  Top Layer w10: v2(470,1425) 500.96,1425 526.43,1450.47 U1.6@555.51,1450.47 ; v2(650,2635) J1.4@900,2635
  Bottom Layer w10: v2(470,1425) 470,1428.99 533,1491.99 533,1550.88 551,1568.88 551,2431 650,2530 v2(650,2635)
SDO: J1.3 U1.4 | length 1674.5
  Top Layer w10: v2@469.49,1519.49 v2@470,1520 ; v2(470,1515) 495,1515 520.16,1489.84 U1.4@555.51,1489.84 ; v2(600,2735) J1.3@900,2735
  Bottom Layer w10: v2@470,1518.99 v2(470,1515) 499,1544 499,1564.96 517,1582.96 517,2652 v2(600,2735)
SH1: NT2.1 U1.19 | length 559.8
  Top Layer w10: U1.19@744.49,1450.47 1006.74,1450.47 1008.09,1451.82 1118.18,1451.82 NT2.1@1249.39,1320.61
